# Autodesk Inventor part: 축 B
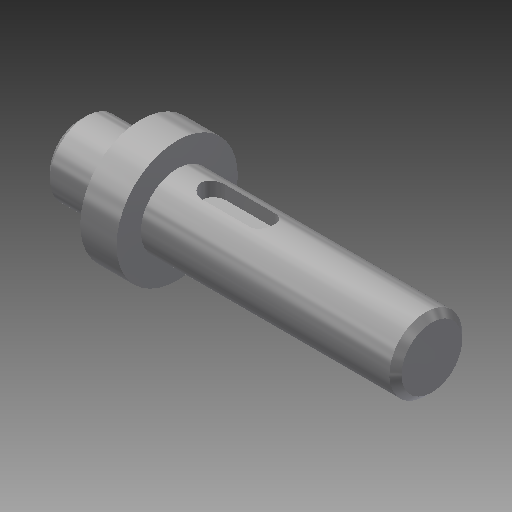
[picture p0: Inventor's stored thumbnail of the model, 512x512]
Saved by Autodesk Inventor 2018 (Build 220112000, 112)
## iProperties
Created: 2020-04
Part Number: 축 B
Material: 강철, 연강
Document SubType Name: Modeling
Designer: mduedu
Density: 7.86 g/cm^3
Mass: 59.9336 g
Surface Area: 29.7709 cm^2
Volume: 7.62514 cm^3
Appearance: 강철
Author: mduedu
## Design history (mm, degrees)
revolve "회전1" stored, may be unused: angle "d11" = 90 deg
sketch "스케치3"
  geometry: L1 (0, -6)-(0, 6) reference; L2 (0, 6)-(10, 6) reference; L3 (10, 6)-(10, 10) reference; L4 (10, 10)-(16, 10) reference; L5 (16, 10)-(16, 6) reference; L6 (16, 6)-(58, 6) reference; L7 (58, 6)-(58, -6) reference; L8 (58, -6)-(16, -6) reference; L9 (16, -6)-(16, -10) reference; L10 (16, -10)-(10, -10) reference; L11 (10, -10)-(10, -6) reference; L12 (10, -6)-(0, -6) reference; L13 (20, 6)-(32, 6); L14 (32, 6)-(32, 3.5); L15 (32, 3.5)-(20, 3.5); L16 (20, 3.5)-(20, 6); 1 further point
  constraints: 8 end point, 2 parallel, 1 horizontal, 1 perpendicular, 1 point on line
  dimensions: "d17" = 12 distance of L14.end L15.end; "d18" = 2.5 distance of L13.end L14.end; "d19" = 4 distance from line of L16 L4.end
extrude "돌출2" cut sketch "스케치3" stored distance "d20" = 4; taper "d21" = 0 deg
fillet "모깎기2" dims "d22" = 2
chamfer "모따기1" distance "d23" = 1; stored, may be unused: second distance "d24" = 2, angle "d25" = 45 deg
chamfer "모따기2" distance "d26" = 1; stored, may be unused: second distance "d27" = 2, angle "d28" = 45 deg
fillet "모깎기3" dims "d29" = 0.3
node "솔리드1"
sketch "스케치1"
  geometry: L1 (0, 0)-(10, 0); L2 (10, 0)-(10, 6); L3 (10, 6)-(0, 6); L4 (0, 6)-(0, 0); L5 (10, 0)-(16, 0); L6 (16, 0)-(16, 10); L7 (16, 10)-(10, 10); L8 (10, 10)-(10, 0); L9 (16, 0)-(58, 0); L10 (58, 0)-(58, 6); L11 (58, 6)-(16, 6); L12 (16, 6)-(16, 0); L13 (58, 0)-(58, 0); L14 (58, 5)-(58, 0)
  constraints: 28 end point, 6 parallel, 4 horizontal, 3 perpendicular
  dimensions: "d2" = 10 distance of L2.end L3.end; "d3" = 6 distance of L6.end L7.end; "d7" = 12 diameter of L11 L9; "d8" = 12 diameter of L3 L1; "d9" = 20 diameter of L7 L5; "d36" = 58 distance between parallel lines of L10 L4
node "절단 모서리 투영2"
